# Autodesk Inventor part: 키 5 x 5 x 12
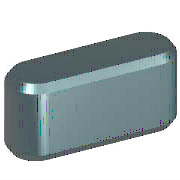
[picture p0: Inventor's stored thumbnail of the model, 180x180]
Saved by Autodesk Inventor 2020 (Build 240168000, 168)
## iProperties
Created: 2012-02
Part Number: 키 5 x 5 x 12
Material: 알루미늄 6061
Description: 키 및 해당 키홈
Document SubType Name: Modeling
Standard: KS B 1311
Designer: mduedu
Standards Organization: KS
Language: ko-KR
Size Designation: 5 x 5 x 12
Categories: <MemberInstance><Categories><Category DisplayName="샤프트 부품" InternalName="7f7aeb1f-a693-4053-b835-cee3144e0d98" Mnemonic="SHFT"><Category DisplayName="키" Interna
Density: 2.7 g/cm^3
Mass: 0.7251 g
Surface Area: 2.43471 cm^2
Volume: 0.268556 cm^3
Appearance: 노란색
IsCustomPart: 1
Author: mduedu
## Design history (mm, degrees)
workplane "Work Plane1"
workplane "Work Plane2"
sketch "스케치1"
  geometry: L1 (2.5, 2.5)-(9.5, 2.5); L2 (9.5, -2.5)-(2.5, -2.5); L3 (0, 9.4)-(0, -7.4) reference; L4 (-5, 0)-(30, 0) reference; L5 (12, 0)-(12, 7); A1 r 2.5 centre (2.5, 0) between (2.5, 2.5) and (2.5, -2.5); A2 r 2.5 centre (9.5, 0) between (9.5, -2.5) and (9.5, 2.5)
  constraints: 6 end point, 5 point on circle, 4 tangent, 3 point on line, 2 centre point, 1 horizontal, 1 parallel, 1 perpendicular
  dimensions: "d0" = 2.5 radius of A1 (= 0.5 x PB); "d13" = 2.5 radius of A2 (= 0.5 x PB); "d14" = 12 distance between parallel lines of L5 L3 (= NLG)
extrude "본체1" new body sketch "스케치1" taper "d3" = 0 deg; stored distance "d4" = 10
workplane "Work Plane3"
body "Solid1"
chamfer "모따기1" distance "d8" = 0.4 (= PHH); stored, may be unused: second distance "d9" = 0.4 (= PHH), angle "d15" = 45 deg
other parameters: "d1" = -3 (= -PNT), "d2" = 2 (= PH - PNT), "NLG" = 12 [user parameter; used in 3 equation terms], "PB" = 5 [user parameter; used in 2 equation terms], "PNT" = 3 [user parameter; used in 2 equation terms], "PH" = 5 [user parameter; used in 1 equation term], "PHH" = 0.4 [user parameter; used in 2 equation terms], "d10" = 0, "d16" = 0, "d17" = 0, "d18" = 0, "WDMIN" = 12 [user parameter], "PLB2" = 12 (= NLG) [user parameter], "WDMAX" = 17 [user parameter], "PLB1" = 12 (= NLG) [user parameter], "RR" = 0.16 [user parameter], "PUEB" = 2.3 [user parameter]
